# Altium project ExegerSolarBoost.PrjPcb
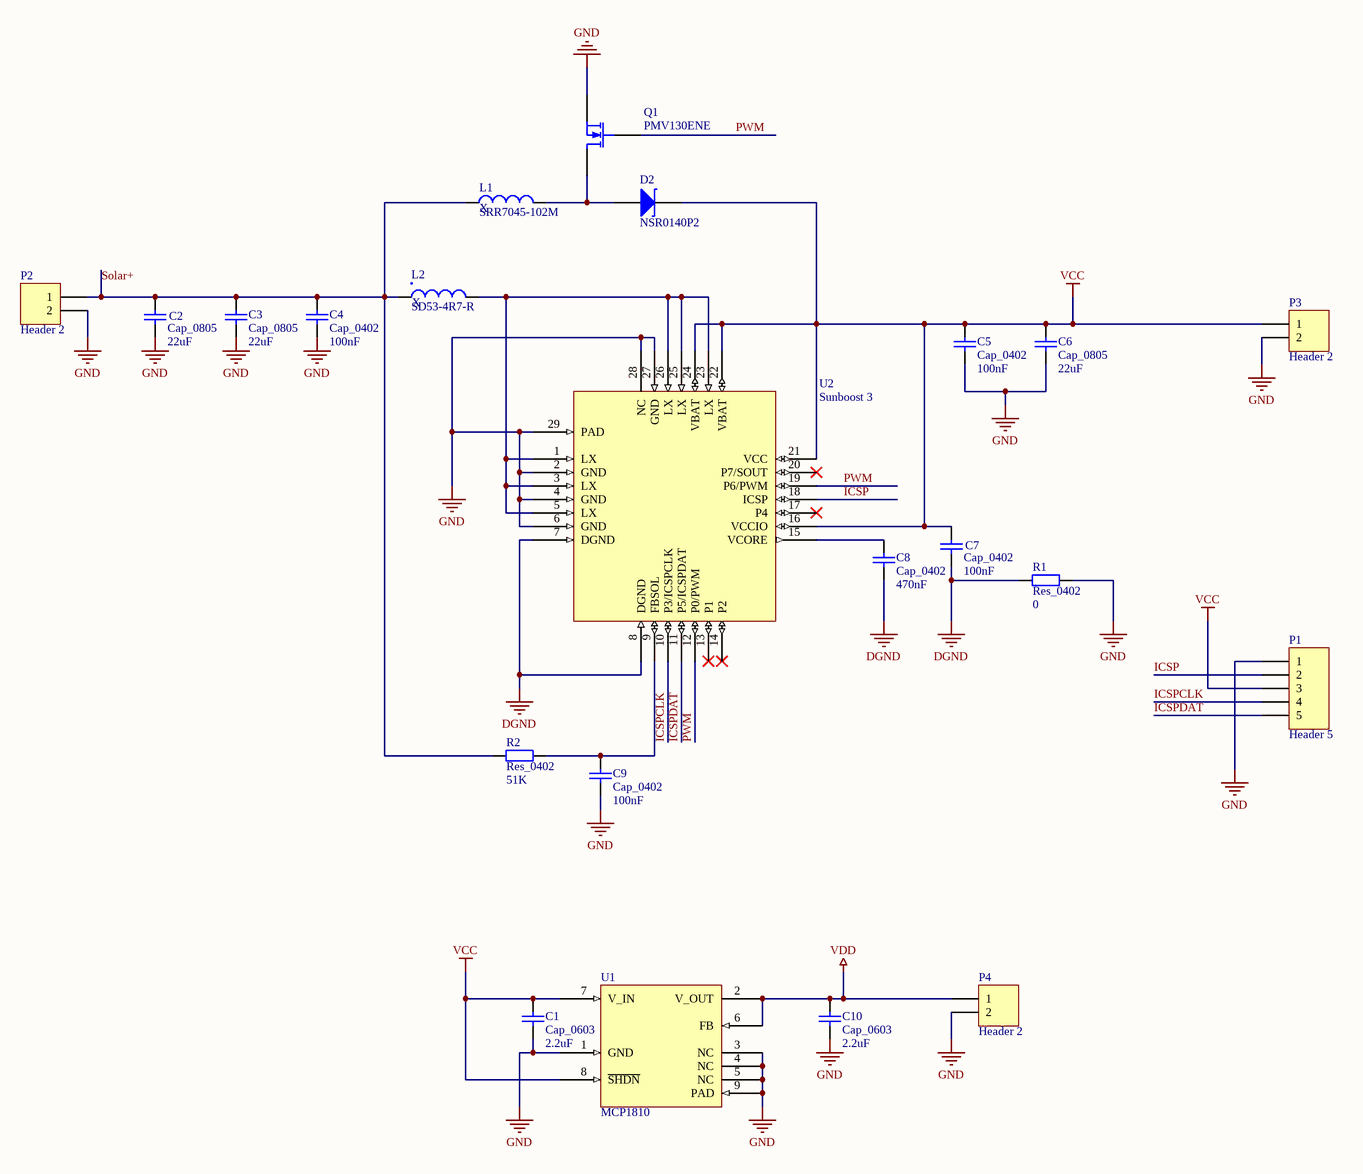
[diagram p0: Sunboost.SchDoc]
Project: 1337; Revision: V1
1 sheet, 22 parts. Net scope: global (net labels, ports and power ports of the same name join across sheets).
Board file: 6C-2L-1550um.PcbDoc

## Sheet Sunboost.SchDoc
size A3; Organization: Altium Limited; Address1: L3, 12a Rodborough Rd; Address2: Frenchs Forest; Address3: NSW; Address4: Australia 2086

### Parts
C1  Cap_0603  value 2.2uF  [0603]
C2  Cap_0805  value 22uF  [0805]
C3  Cap_0805  value 22uF  [0805]
C4  Cap_0402  value 100nF  [0402]
C5  Cap_0402  value 100nF  [0402]
C6  Cap_0805  value 22uF  [0805]
C7  Cap_0402  value 100nF  [0402]
C8  Cap_0402  value 470nF  [0402]
C9  Cap_0402  value 100nF  [0402]
C10  Cap_0603  value 2.2uF  [0603]
D2  NSR0140P2  [SOD-923]
L1  SRR7045-102M  value X  [SRR7045-102M]
L2  SD53-4R7-R  value X  [SD53-4R7-R]
P1  Header 5  [HDR1X5]
P2  Header 2  [HDR1X2]
P3  Header 2  [HDR1X2]
P4  Header 2  [HDR1X2]
Q1  PMV130ENE  [SOT-23]
R1  Res_0402  value 0  [0402]
R2  Res_0402  value 51K  [0402]
U1  MCP1810  [VDFN8]
U2  Sunboost 3  [28-QFN_0.4mm]

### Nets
DGND: C7.1 C8.1 R1.1 U2.7(DGND) U2.8(DGND)
GND: C1.1 C2.1 C3.1 C4.1 C5.1 C6.1 C9.1 C10.1 P1.1 P2.2 P3.2 P4.2 Q1.2(S) R1.2 U1.1(GND) U1.3(NC) U1.4(NC) U1.5(NC) U1.9(PAD) U2.2(GND) U2.4(GND) U2.6(GND) U2.27(GND) U2.28(NC) U2.29(PAD)
VCC: C1.2 C5.2 C6.2 C7.2 D2.1(K) P1.3 P3.1 U1.7(V_IN) U1.8(~{SHDN}) U2.16(VCCIO) U2.21(VCC) U2.22(VBAT) U2.24(VBAT)
VDD: C10.2 P4.1 U1.2(V_OUT) U1.6(FB)
ICSP: P1.2 U2.18(ICSP)
ICSPCLK: P1.4 U2.10(P3/ICSPCLK)
ICSPDAT: P1.5 U2.11(P5/ICSPDAT)
PWM: Q1.1(G) U2.12(P0/PWM) U2.19(P6/PWM)
Solar+: C2.2 C3.2 C4.2 L1.1 L2.1 P2.1 R2.1
NetC8_2: C8.2 U2.15(VCORE)
NetC9_2: C9.2 R2.2 U2.9(FBSOL)
NetD2_2: D2.2(A) L1.2 Q1.3(D)
NetL2_2: L2.2 U2.1(LX) U2.3(LX) U2.5(LX) U2.23(LX) U2.25(LX) U2.26(LX)

Not connected (* = marked no-connect by the designer): U2 13(P1)* 14(P2)* 17(P4)* 20(P7/SOUT)*

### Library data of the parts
C1 C10 = Cap_0603: Capacitor
C2 C3 C6 = Cap_0805: Capacitor
C4 C5 C7-C9 = Cap_0402: Capacitor
D2 = NSR0140P2: Typical INFRARED GaAs LED
L1 = SRR7045-102M: Inductor
L2 = SD53-4R7-R: Inductor
P1 = Header 5: Header, 5-Pin
P2-P4 = Header 2: Header, 2-Pin
Q1 = PMV130ENE: N-Channel MOSFET
R1 R2 = Res_0402: Resistor
U1 = MCP1810: 3V Regulator, 150 mA
U2 = Sunboost 3: Initvation Sunboost 3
